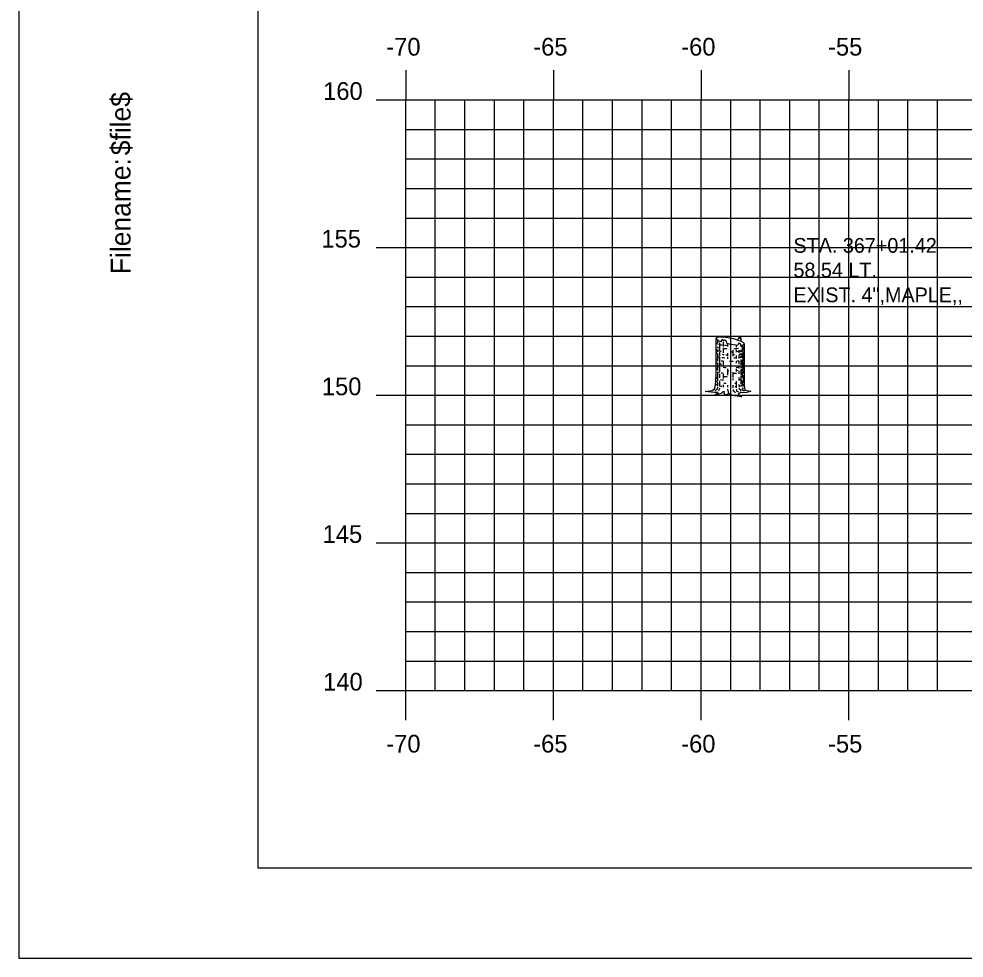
# Model space of a CAD drawing. Extents: x 1147633 to 1147803, y 608981 to 609091.
# Drawn here: x 1147633.36 to 1147665.35, y 608981.28 to 609013.08 of the extents above; entities that cross this region are included whole.
import ezdxf

# ---------------------------------------------------------------- set-up
doc = ezdxf.new("R2010")
doc.units = 0
for name, color, linetype in [('BORDER', 7, 'Continuous'), ('D_Text_Monospaced', 7, 'Continuous'), ('H_V ANNOTATION', 7, 'Continuous'), ('MAJOR', 7, 'Continuous'), ('MINOR', 7, 'Continuous'), ('PLOT BOUNDARY', 7, 'Continuous'), ('S_Trees_Decid_NonPay', 7, 'Continuous')]:
    doc.layers.add(name, color=color, linetype=linetype)

msp = doc.modelspace()

# ---------------------------------------------------------------- linework, layer by layer
at = {"layer": 'BORDER'}
msp.add_lwpolyline([(1147641.454, 608984.335), (1147801.454, 608984.335), (1147801.454, 609089.335), (1147641.454, 609089.335)], close=True, dxfattribs=at)
at = {"layer": 'MAJOR'}
for p, q in [((1147646.454, 609011.337), (1147646.454, 609010.335)), ((1147651.454, 609011.337), (1147651.454, 609010.335)), ((1147656.454, 609011.337), (1147656.454, 609010.335)), ((1147661.454, 609011.337), (1147661.454, 609010.335)), ((1147645.452, 609010.335), (1147646.454, 609010.335)), ((1147646.454, 609010.335), (1147786.454, 609010.335)), ((1147646.454, 608990.335), (1147646.454, 609010.335)), ((1147646.454, 608990.335), (1147646.454, 609010.335)), ((1147646.454, 609010.335), (1147786.454, 609010.335)), ((1147651.454, 608990.335), (1147651.454, 609010.335)), ((1147656.454, 608990.335), (1147656.454, 609010.335)), ((1147661.454, 608990.335), (1147661.454, 609010.335)), ((1147645.452, 609005.335), (1147646.454, 609005.335)), ((1147646.454, 609005.335), (1147786.454, 609005.335)), ((1147645.452, 609000.335), (1147646.454, 609000.335)), ((1147646.454, 609000.335), (1147786.454, 609000.335)), ((1147645.452, 608995.335), (1147646.454, 608995.335)), ((1147646.454, 608995.335), (1147786.454, 608995.335)), ((1147645.452, 608990.335), (1147646.454, 608990.335)), ((1147646.454, 608990.335), (1147786.454, 608990.335)), ((1147646.454, 608990.335), (1147786.454, 608990.335)), ((1147646.454, 608989.333), (1147646.454, 608990.335)), ((1147651.454, 608989.333), (1147651.454, 608990.335)), ((1147656.454, 608989.333), (1147656.454, 608990.335)), ((1147661.454, 608989.333), (1147661.454, 608990.335))]:
    msp.add_line(p, q, dxfattribs=at)
at = {"layer": 'MINOR'}
for p, q in [((1147647.454, 608990.335), (1147647.454, 609010.335)), ((1147648.454, 608990.335), (1147648.454, 609010.335)), ((1147649.454, 608990.335), (1147649.454, 609010.335)), ((1147650.454, 608990.335), (1147650.454, 609010.335)), ((1147652.454, 608990.335), (1147652.454, 609010.335)), ((1147653.454, 608990.335), (1147653.454, 609010.335)), ((1147654.454, 608990.335), (1147654.454, 609010.335)), ((1147655.454, 608990.335), (1147655.454, 609010.335)), ((1147657.454, 608990.335), (1147657.454, 609010.335)), ((1147658.454, 608990.335), (1147658.454, 609010.335)), ((1147659.454, 608990.335), (1147659.454, 609010.335)), ((1147660.454, 608990.335), (1147660.454, 609010.335)), ((1147662.454, 608990.335), (1147662.454, 609010.335)), ((1147663.454, 608990.335), (1147663.454, 609010.335)), ((1147664.454, 608990.335), (1147664.454, 609010.335)), ((1147646.454, 609009.335), (1147786.454, 609009.335)), ((1147646.454, 609009.335), (1147647.456, 609009.335)), ((1147646.454, 609008.335), (1147786.454, 609008.335)), ((1147646.454, 609008.335), (1147647.456, 609008.335)), ((1147646.454, 609007.335), (1147786.454, 609007.335)), ((1147646.454, 609007.335), (1147647.456, 609007.335)), ((1147646.454, 609006.335), (1147786.454, 609006.335)), ((1147646.454, 609006.335), (1147647.456, 609006.335)), ((1147646.454, 609004.335), (1147786.454, 609004.335)), ((1147646.454, 609004.335), (1147647.456, 609004.335)), ((1147646.454, 609003.335), (1147786.454, 609003.335)), ((1147646.454, 609003.335), (1147647.456, 609003.335)), ((1147646.454, 609002.335), (1147786.454, 609002.335)), ((1147646.454, 609002.335), (1147647.456, 609002.335)), ((1147646.454, 609001.335), (1147786.454, 609001.335)), ((1147646.454, 609001.335), (1147647.456, 609001.335)), ((1147646.454, 608999.335), (1147786.454, 608999.335)), ((1147646.454, 608999.335), (1147647.456, 608999.335)), ((1147646.454, 608998.335), (1147786.454, 608998.335)), ((1147646.454, 608998.335), (1147647.456, 608998.335)), ((1147646.454, 608997.335), (1147786.454, 608997.335)), ((1147646.454, 608997.335), (1147647.456, 608997.335)), ((1147646.454, 608996.335), (1147786.454, 608996.335)), ((1147646.454, 608996.335), (1147647.456, 608996.335)), ((1147646.454, 608994.335), (1147786.454, 608994.335)), ((1147646.454, 608994.335), (1147647.456, 608994.335)), ((1147646.454, 608993.335), (1147786.454, 608993.335)), ((1147646.454, 608993.335), (1147647.456, 608993.335)), ((1147646.454, 608992.335), (1147786.454, 608992.335)), ((1147646.454, 608992.335), (1147647.456, 608992.335)), ((1147646.454, 608991.335), (1147786.454, 608991.335)), ((1147646.454, 608991.335), (1147647.456, 608991.335))]:
    msp.add_line(p, q, dxfattribs=at)
at = {"layer": 'PLOT BOUNDARY'}
msp.add_lwpolyline([(1147633.361, 608981.276), (1147803.361, 608981.276), (1147803.361, 609091.276), (1147633.361, 609091.276)], close=True, dxfattribs=at)
at = {"layer": 'S_Trees_Decid_NonPay'}
for p, q in [((1147657.013, 609002.207), (1147657.013, 609002.113)), ((1147657.081, 609002.121), (1147657.081, 609001.82)), ((1147657.2, 609002.138), (1147657.2, 609001.99)), ((1147657.347, 609002.092), (1147657.347, 609001.985)), ((1147657.644, 609002.039), (1147657.644, 609001.961)), ((1147657.802, 609002.029), (1147657.802, 609001.977)), ((1147657.845, 609002.034), (1147657.845, 609001.816)), ((1147657.013, 609001.887), (1147657.013, 609001.804)), ((1147657.013, 609001.734), (1147657.013, 609001.483)), ((1147657.081, 609001.791), (1147657.081, 609001.66)), ((1147657.2, 609001.942), (1147657.2, 609001.773)), ((1147657.347, 609001.757), (1147657.347, 609001.67)), ((1147657.527, 609001.856), (1147657.527, 609001.656)), ((1147657.644, 609001.874), (1147657.644, 609001.789)), ((1147657.731, 609001.856), (1147657.731, 609001.769)), ((1147657.731, 609001.699), (1147657.731, 609001.578)), ((1147657.802, 609001.874), (1147657.802, 609001.791)), ((1147657.802, 609001.757), (1147657.802, 609001.683)), ((1147657.845, 609001.747), (1147657.845, 609001.596)), ((1147657.871, 609001.964), (1147657.871, 609001.882)), ((1147657.871, 609001.812), (1147657.871, 609001.683)), ((1147657.013, 609001.4), (1147657.013, 609001.17)), ((1147657.081, 609001.626), (1147657.081, 609001.345)), ((1147657.2, 609001.467), (1147657.2, 609001.318)), ((1147657.347, 609001.635), (1147657.347, 609001.565)), ((1147657.644, 609001.679), (1147657.644, 609001.578)), ((1147657.644, 609001.493), (1147657.644, 609001.417)), ((1147657.731, 609001.502), (1147657.731, 609001.388)), ((1147657.802, 609001.656), (1147657.802, 609001.596)), ((1147657.802, 609001.543), (1147657.802, 609001.362)), ((1147657.845, 609001.491), (1147657.845, 609001.413)), ((1147657.845, 609001.386), (1147657.845, 609001.279)), ((1147657.871, 609001.66), (1147657.871, 609001.478)), ((1147657.871, 609001.431), (1147657.871, 609001.184)), ((1147657.013, 609001.1), (1147657.013, 609000.939)), ((1147657.081, 609001.275), (1147657.081, 609001.131)), ((1147657.081, 609001.06), (1147657.081, 609000.919)), ((1147657.347, 609001.232), (1147657.347, 609001.009)), ((1147657.527, 609001.118), (1147657.527, 609000.931)), ((1147657.644, 609001.232), (1147657.644, 609001.135)), ((1147657.731, 609001.326), (1147657.731, 609001.244)), ((1147657.731, 609001.158), (1147657.731, 609001.06)), ((1147657.802, 609001.33), (1147657.802, 609001.248)), ((1147657.802, 609001.194), (1147657.802, 609001.024)), ((1147657.845, 609001.244), (1147657.845, 609001.143)), ((1147657.845, 609001.118), (1147657.845, 609000.935)), ((1147657.871, 609001.165), (1147657.871, 609001.071)), ((1147657.013, 609000.923), (1147657.013, 609000.818)), ((1147657.013, 609000.781), (1147657.013, 609000.657)), ((1147657.081, 609000.818), (1147657.081, 609000.637)), ((1147657.2, 609001.049), (1147657.2, 609000.896)), ((1147657.527, 609000.9), (1147657.527, 609000.847)), ((1147657.644, 609000.81), (1147657.644, 609000.585)), ((1147657.731, 609000.931), (1147657.731, 609000.832)), ((1147657.802, 609000.99), (1147657.802, 609000.711)), ((1147657.845, 609000.832), (1147657.845, 609000.641)), ((1147657.873, 609001.018), (1147657.872, 609000.758)), ((1147657.081, 609000.577), (1147657.039, 609000.48)), ((1147657.2, 609000.684), (1147657.2, 609000.606)), ((1147657.347, 609000.676), (1147657.347, 609000.61)), ((1147657.387, 609000.39), (1147657.352, 609000.536)), ((1147657.527, 609000.671), (1147657.527, 609000.581)), ((1147657.731, 609000.703), (1147657.731, 609000.644)), ((1147657.802, 609000.658), (1147657.802, 609000.633)), ((1147657.843, 609000.593), (1147657.877, 609000.542)), ((1147657.925, 609000.472), (1147657.857, 609000.503)), ((1147657.871, 609000.719), (1147657.871, 609000.645))]:
    msp.add_line(p, q, dxfattribs=at)
for points in [[(1147657.818, 609002.152), (1147657.814, 609002.247), (1147657.799, 609002.22), (1147657.799, 609002.341), (1147657.778, 609002.278), (1147657.764, 609002.31), (1147657.747, 609002.255), (1147657.731, 609002.272), (1147657.713, 609002.263), (1147657.694, 609002.196)], [(1147657.913, 609002.072), (1147657.913, 609000.66), (1147657.935, 609000.511), (1147658.139, 609000.468), (1147657.999, 609000.433), (1147657.78, 609000.414), (1147657.711, 609000.371), (1147657.832, 609000.282), (1147657.501, 609000.326), (1147657.387, 609000.39), (1147657.295, 609000.33), (1147657.239, 609000.408), (1147657.247, 609000.445), (1147657.186, 609000.447), (1147657.134, 609000.39), (1147656.902, 609000.338), (1147657.029, 609000.427), (1147656.897, 609000.429), (1147656.589, 609000.466), (1147656.828, 609000.497), (1147656.906, 609000.555), (1147656.944, 609000.676), (1147656.961, 609001.03), (1147656.961, 609002.263)], [(1147657.326, 609002.097), (1147657.317, 609002.164), (1147657.293, 609002.169), (1147657.284, 609002.204), (1147657.253, 609002.189), (1147657.239, 609002.204), (1147657.215, 609002.181), (1147657.192, 609002.189), (1147657.179, 609002.238), (1147657.171, 609002.195), (1147657.141, 609002.204), (1147657.137, 609002.152)], [(1147657.795, 609002.028), (1147657.778, 609002.09), (1147657.756, 609002.078), (1147657.725, 609002.113), (1147657.692, 609002.035)], [(1147657.011, 609000.614), (1147657.002, 609000.538), (1147656.924, 609000.488)], [(1147657.536, 609000.532), (1147657.536, 609000.495), (1147657.587, 609000.464), (1147657.604, 609000.414)], [(1147657.647, 609000.538), (1147657.653, 609000.468), (1147657.717, 609000.455)], [(1147657.795, 609000.503), (1147657.751, 609000.538), (1147657.744, 609000.585)], [(1147657.873, 609000.519), (1147657.795, 609000.503), (1147657.778, 609000.459)]]:
    msp.add_lwpolyline(points, dxfattribs=at)
for centre, radius, start, end in [((1147656.98, 609002.116), 0.0191, 163.9485, 180), ((1147656.98, 609002.116), 0.0191, 180, 196.0515), ((1147656.98, 609002.263), 0.0179, 152.1168, 168.1723), ((1147656.98, 609002.263), 0.0179, 168.1723, 184.2278), ((1147656.985, 609002.264), 0.0237, 184.2278, 198.1723), ((1147656.986, 609002.118), 0.0252, 196.0515, 210), ((1147656.995, 609002.267), 0.0336, 198.1723, 216.9486), ((1147656.985, 609002.261), 0.0237, 138.1723, 152.1168), ((1147656.995, 609002.123), 0.0356, 210, 228.7494), ((1147656.992, 609002.254), 0.0336, 119.396, 138.1723), ((1147657.043, 609002.303), 0.0935, 216.9486, 228.1723), ((1147657.036, 609002.17), 0.0984, 228.7494, 240), ((1147657.021, 609002.202), 0.0935, 108.1723, 119.396), ((1147657.195, 609002.473), 0.322, 228.1723, 250.2902), ((1147657.15, 609002.367), 0.326, 240, 248.3243), ((1147657.093, 609001.985), 0.322, 86.0543, 108.1723), ((1147657.15, 609002.367), 0.326, 257.8036, 261.8968), ((1147657.932, 609004.53), 2.507, 250.2902, 251.5281), ((1147657.436, 609004.377), 2.356, 261.8968, 263.2799), ((1147656.942, 608999.805), 2.507, 78.1723, 86.0543), ((1147657.436, 609004.377), 2.356, 265.24, 267.8386), ((1147657.932, 609004.53), 2.507, 255.9987, 258.1723), ((1147657.932, 609004.53), 2.507, 258.1723, 264.5013), ((1147656.942, 608999.805), 2.507, 70.2902, 78.1723), ((1147657.679, 609001.862), 0.322, 48.1723, 70.2902), ((1147657.781, 609002.35), 0.322, 272.4479, 288.1723), ((1147657.853, 609002.133), 0.0935, 288.1723, 299.396), ((1147657.832, 609002.032), 0.0935, 36.9486, 48.1723), ((1147657.882, 609002.081), 0.0336, 299.396, 318.1723), ((1147657.879, 609002.068), 0.0336, 18.1723, 36.9486), ((1147657.889, 609002.074), 0.0237, 318.1723, 332.1168), ((1147657.895, 609002.072), 0.0179, 332.1168, 348.1723), ((1147657.889, 609002.071), 0.0237, 4.2278, 18.1723), ((1147657.895, 609002.072), 0.0179, 348.1723, 4.2278), ((1147656.98, 609001.902), 0.0191, 163.9485, 180), ((1147656.98, 609001.902), 0.0191, 180, 196.0515), ((1147656.98, 609001.799), 0.0191, 163.9485, 180), ((1147656.98, 609001.799), 0.0191, 180, 196.0515), ((1147656.986, 609001.903), 0.0252, 196.0515, 210), ((1147656.986, 609001.801), 0.0252, 196.0515, 210), ((1147656.995, 609001.909), 0.0356, 210, 228.7494), ((1147656.995, 609001.806), 0.0356, 210, 228.7494), ((1147657.036, 609001.956), 0.0984, 228.7494, 240), ((1147657.036, 609001.853), 0.0984, 228.7494, 240), ((1147657.15, 609002.153), 0.326, 240, 243.5719), ((1147657.15, 609002.05), 0.326, 240, 243.243), ((1147657.15, 609002.254), 0.326, 240.9099, 257.8036), ((1147657.15, 609002.153), 0.326, 250.4167, 261.8968), ((1147657.15, 609002.05), 0.326, 251.6831, 257.8036), ((1147657.436, 609004.163), 2.356, 261.8968, 262.5519), ((1147657.436, 609004.06), 2.356, 263.3413, 264.9946), ((1147657.436, 609004.264), 2.356, 264.242, 267.3673), ((1147657.436, 609004.06), 2.356, 266.5036, 267.8386), ((1147657.436, 609004.163), 2.356, 270.8119, 272.1981), ((1147657.436, 609004.06), 2.356, 272.1981, 273.9741), ((1147657.436, 609004.264), 2.356, 273.1481, 276.7734), ((1147657.436, 609004.163), 2.356, 275.0647, 278.1032), ((1147657.436, 609004.06), 2.356, 277.3838, 278.1032), ((1147657.723, 609002.153), 0.326, 278.1032, 279.0854), ((1147657.723, 609002.05), 0.326, 278.1032, 284.0382), ((1147657.723, 609002.254), 0.326, 291.9506, 300), ((1147657.723, 609002.153), 0.326, 291.9506, 300), ((1147657.836, 609002.057), 0.0984, 300, 311.2506), ((1147657.836, 609001.956), 0.0984, 300, 311.2506), ((1147657.878, 609002.01), 0.0356, 311.2506, 330), ((1147657.878, 609001.909), 0.0356, 311.2506, 330), ((1147657.887, 609002.004), 0.0252, 330, 343.9485), ((1147657.887, 609001.903), 0.0252, 330, 343.9485), ((1147657.893, 609002.003), 0.0191, 343.9485, 360), ((1147657.893, 609001.902), 0.0191, 343.9485, 360), ((1147657.893, 609001.799), 0.0191, 343.9485, 360), ((1147657.893, 609002.003), 0.0191, 360, 6.1128), ((1147657.893, 609001.902), 0.0191, 360, 6.1128), ((1147657.893, 609001.799), 0.0191, 360, 6.1128), ((1147657.893, 609001.694), 0.0191, 360, 6.1128), ((1147656.98, 609001.579), 0.0191, 163.9485, 180), ((1147656.98, 609001.579), 0.0191, 180, 196.0515), ((1147656.986, 609001.58), 0.0252, 196.0515, 210), ((1147656.981, 609001.464), 0.0191, 163.9485, 180), ((1147656.981, 609001.464), 0.0191, 180, 196.0515), ((1147656.987, 609001.466), 0.0252, 196.0515, 210), ((1147656.995, 609001.586), 0.0356, 210, 228.7494), ((1147656.996, 609001.471), 0.0356, 210, 228.7494), ((1147657.036, 609001.633), 0.0984, 228.7494, 240), ((1147657.037, 609001.518), 0.0984, 228.7494, 240), ((1147657.15, 609001.83), 0.326, 240, 245.1545), ((1147657.151, 609001.716), 0.326, 240, 247.8656), ((1147657.15, 609001.945), 0.326, 245.1545, 257.8036), ((1147657.151, 609001.716), 0.326, 257.6699, 261.8968), ((1147657.437, 609003.726), 2.356, 261.8968, 262.8615), ((1147657.436, 609003.84), 2.356, 262.6588, 264.7911), ((1147657.436, 609003.955), 2.356, 263.2682, 265.6362), ((1147657.436, 609003.84), 2.356, 269.5578, 270), ((1147657.436, 609003.84), 2.356, 270, 272.414), ((1147657.436, 609003.955), 2.356, 273.0067, 275.0647), ((1147657.436, 609003.84), 2.356, 275.0647, 277.1868), ((1147657.436, 609003.955), 2.356, 277.1868, 278.1032), ((1147657.723, 609001.945), 0.326, 278.1032, 284.0382), ((1147657.723, 609001.83), 0.326, 284.0382, 300), ((1147657.723, 609001.716), 0.326, 283.9036, 291.8098), ((1147657.723, 609001.945), 0.326, 291.9506, 300), ((1147657.723, 609001.716), 0.326, 297.0058, 300), ((1147657.836, 609001.748), 0.0984, 300, 311.2506), ((1147657.836, 609001.633), 0.0984, 300, 311.2506), ((1147657.837, 609001.518), 0.0984, 300, 311.2506), ((1147657.878, 609001.701), 0.0356, 311.2506, 330), ((1147657.878, 609001.586), 0.0356, 311.2506, 330), ((1147657.879, 609001.471), 0.0356, 311.2506, 330), ((1147657.887, 609001.696), 0.0252, 330, 343.9485), ((1147657.887, 609001.58), 0.0252, 330, 343.9485), ((1147657.888, 609001.466), 0.0252, 330, 343.9485), ((1147657.893, 609001.694), 0.0191, 343.9485, 360), ((1147657.893, 609001.579), 0.0191, 343.9485, 360), ((1147657.893, 609001.579), 0.0191, 360, 6.1128), ((1147657.893, 609001.464), 0.0191, 0, 6.1128), ((1147657.893, 609001.464), 0.0191, 343.9485, 360), ((1147656.978, 609001.364), 0.0191, 163.9485, 180), ((1147656.98, 609001.259), 0.0191, 163.9485, 180), ((1147656.98, 609001.259), 0.0191, 180, 196.0515), ((1147656.986, 609001.261), 0.0252, 196.0515, 210), ((1147656.995, 609001.266), 0.0356, 210, 228.7494), ((1147657.036, 609001.313), 0.0984, 228.7494, 240), ((1147657.148, 609001.615), 0.326, 240, 256.9079), ((1147657.15, 609001.511), 0.326, 240, 245.1545), ((1147657.15, 609001.42), 0.326, 241.939, 253.9183), ((1147657.436, 609003.43), 2.356, 262.5843, 264.4865), ((1147657.434, 609003.625), 2.356, 264.3443, 266.8529), ((1147657.436, 609003.521), 2.356, 267.8386, 269.0054), ((1147657.436, 609003.43), 2.356, 272.1981, 275.2726), ((1147657.434, 609003.625), 2.356, 274.9734, 277.2455), ((1147657.436, 609003.521), 2.356, 275.0647, 276.428), ((1147657.723, 609001.511), 0.326, 284.0382, 291.9506), ((1147657.72, 609001.615), 0.326, 292.4049, 300), ((1147657.723, 609001.511), 0.326, 297.1525, 300), ((1147657.834, 609001.418), 0.0984, 300, 311.2506), ((1147657.836, 609001.313), 0.0984, 300, 311.2506), ((1147657.875, 609001.371), 0.0356, 311.2506, 330), ((1147657.878, 609001.266), 0.0356, 311.2506, 330), ((1147657.884, 609001.366), 0.0252, 330, 343.9485), ((1147657.89, 609001.364), 0.0191, 0, 6.1128), ((1147657.89, 609001.364), 0.0191, 343.9485, 360), ((1147657.887, 609001.261), 0.0252, 330, 343.9485), ((1147657.893, 609001.259), 0.0191, 343.9485, 360), ((1147657.893, 609001.259), 0.0191, 360, 6.1128), ((1147657.893, 609001.169), 0.0191, 360, 6.1128), ((1147656.971, 609000.83), 0.0191, 163.9485, 180), ((1147656.971, 609000.83), 0.0191, 180, 196.0515), ((1147656.977, 609000.831), 0.0252, 196.0515, 210), ((1147656.986, 609000.837), 0.0356, 210, 228.7494), ((1147656.976, 609000.94), 0.0191, 163.9485, 180), ((1147656.976, 609000.94), 0.0191, 180, 196.0515), ((1147656.982, 609000.942), 0.0252, 196.0515, 210), ((1147656.991, 609000.947), 0.0356, 210, 228.7494), ((1147657.027, 609000.884), 0.0984, 228.7494, 240), ((1147657.032, 609000.994), 0.0984, 228.7494, 240), ((1147657.141, 609001.081), 0.326, 240, 241.9097), ((1147657.146, 609001.192), 0.326, 240, 245.9375), ((1147657.432, 609003.202), 2.356, 262.2226, 264.4852), ((1147657.436, 609003.317), 2.356, 264.242, 267.469), ((1147657.427, 609003.091), 2.356, 264.9089, 266.8158), ((1147657.427, 609003.091), 2.356, 274.1864, 275.2829), ((1147657.432, 609003.202), 2.356, 277.2863, 278.1032), ((1147657.718, 609001.192), 0.326, 278.1032, 284.7741), ((1147657.723, 609001.307), 0.326, 284.0382, 291.9506), ((1147657.714, 609001.081), 0.326, 293.6544, 300), ((1147657.832, 609000.994), 0.0984, 300, 311.2506), ((1147657.874, 609000.947), 0.0356, 311.2506, 330), ((1147657.883, 609000.942), 0.0252, 330, 343.9485), ((1147657.889, 609000.94), 0.0191, 343.9485, 360), ((1147657.889, 609000.94), 0.0191, 360, 6.1128), ((1147656.966, 609000.719), 0.0191, 163.9485, 180), ((1147656.966, 609000.719), 0.0191, 180, 196.0515), ((1147656.971, 609000.721), 0.0252, 196.0515, 210), ((1147656.98, 609000.726), 0.0356, 210, 228.7494), ((1147657.022, 609000.774), 0.0984, 228.7494, 240), ((1147657.136, 609000.971), 0.326, 240, 247.9161), ((1147657.136, 609000.971), 0.326, 260.3834, 261.8968), ((1147657.422, 609002.981), 2.356, 261.8968, 263.5333), ((1147657.422, 609002.981), 2.356, 274.5551, 275.4167), ((1147657.422, 609002.981), 2.356, 277.5403, 278.1032), ((1147657.708, 609000.971), 0.326, 278.1032, 294.7094), ((1147657.822, 609000.774), 0.0984, 300, 311.2506), ((1147657.863, 609000.726), 0.0356, 311.2506, 330), ((1147657.872, 609000.721), 0.0252, 330, 343.9485), ((1147657.878, 609000.719), 0.0191, 0, 6.1128), ((1147657.878, 609000.719), 0.0191, 343.9485, 360)]:
    msp.add_arc(centre, radius, start, end, dxfattribs=at)

# ---------------------------------------------------------------- texts
at = {"layer": 'BORDER'}
for s, p in [('$file$', (1147637.139, 609008.461)), ('Filename:', (1147637.139, 609004.433))]:
    msp.add_text(s, height=0.6696, rotation=90, dxfattribs=at).set_placement(p)
at = {"layer": 'D_Text_Monospaced'}
for s, height, p in [('STA. 367+01.42', 0.49998, (1147659.579, 609005.158)), ('58.54 LT.', 0.5, (1147659.579, 609004.324)), ('EXIST. 4",MAPLE,,', 0.49998, (1147659.579, 609003.484))]:
    msp.add_text(s, height=height, dxfattribs=at).set_placement(p)
at = {"layer": 'H_V ANNOTATION'}
for s, p in [('-70', (1147645.796, 609011.835)), ('-65', (1147650.772, 609011.835)), ('-60', (1147655.78, 609011.835)), ('-55', (1147660.75, 609011.835)), ('160', (1147643.659, 609010.335)), ('155', (1147643.6, 609005.335)), ('150', (1147643.616, 609000.335)), ('145', (1147643.643, 608995.335)), ('140', (1147643.659, 608990.335)), ('-70', (1147645.796, 608988.235)), ('-65', (1147650.772, 608988.235)), ('-60', (1147655.78, 608988.235)), ('-55', (1147660.75, 608988.235))]:
    msp.add_text(s, height=0.6, dxfattribs=at).set_placement(p)
at = {"layer": 'MAJOR'}
msp.add_text('-', height=0.006, dxfattribs=at).set_placement((1147646.45, 608990.335))

doc.saveas('drawing.dxf')
